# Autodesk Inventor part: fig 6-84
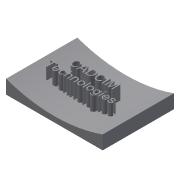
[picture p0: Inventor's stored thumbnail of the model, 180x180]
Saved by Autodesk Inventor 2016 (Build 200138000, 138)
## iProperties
Shininess: 64.0
Length Units: 11269
Angle Units: 11279
Time Units: 11290
Mass Units: 11283
Length Display Precision: 3
Angle Display Precision: 2
Compacted: True
Part Number: fig 6-84
Document SubType Name: Modeling
Created: 2002-12
Designer: deepak
Density: 1 g/cm^3
Material: Generic
Appearance: Default
Density: 0.0
Volumn: 0.0
Area: 0.0
PropertySet Name: Model Information
Control State: 0
Master: False
Checked Out: False
Author: deepak
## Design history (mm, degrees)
sketch "Sketch1"
  geometry: L1 (-39.922, 33.786)-(30.103, 33.786); L2 (30.103, 33.786)-(30.103, -17.894); L3 (30.103, -17.894)-(-39.922, -17.894); L4 (-39.922, -17.894)-(-39.922, 33.786)
  constraints: 8 end point, 2 parallel, 1 horizontal, 1 perpendicular
extrude "Extrusion1" new body sketch "Sketch1" distance "d0" = 10; taper "d1" = 0 deg
workplane "Work Plane1"
sketch "Sketch2"
  geometry: L1 (-37.656, 15.034)-(26.28, 15.034); L2 (26.28, 15.034)-(26.28, 10.168); L3 (26.28, 10.168)-(-37.656, 10.168); L4 (-37.656, 10.168)-(-37.656, 15.034)
  constraints: 2 other
sketch "Sketch3"
  geometry: L1 (70.026, 10)-(0, 10) reference; A1 r 105 centre (35.013, 108.99) between (0, 10) and (70.026, 10)
  constraints: 2 point on circle, 1 centre point
  dimensions: "d5" = 105 radius of A1
extrude "Extrusion2" cut sketch "Sketch3" stored distance "d3" = 10; taper "d4" = 0 deg
emboss "Emboss4" sketch "Sketch2" dims "d14" = 1, "d15" = 0
body "Solid1"
other parameters: "d2" = 5
